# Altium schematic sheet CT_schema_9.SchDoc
size 147 x 119 mm
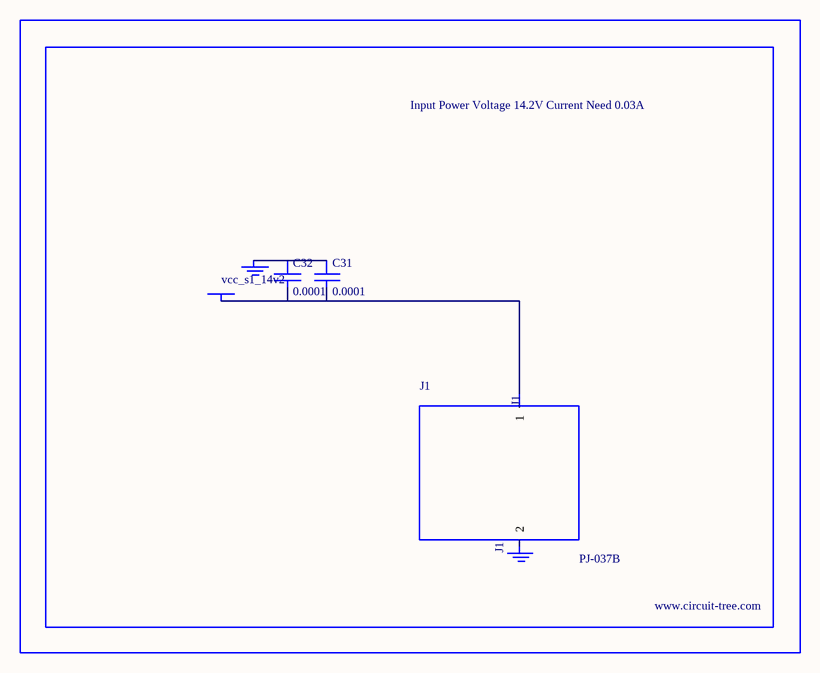
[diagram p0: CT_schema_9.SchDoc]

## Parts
BORDER8  (no value)
C31  0.0001  [EXV-9H]
C32  0.0001  [EXV-9H]
GND_INSTANCE_8_0  (no value)
GND_INSTANCE_8_1  (no value)
J1  PJ-037B  [PJ-037B_PACKAGE]
POWER_INSTANCE_8_0  vcc_s1_14v2

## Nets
NetC31_1: C31.1 C32.1 GND_INSTANCE_8_0.0(GND)
NetC31_2: C31.2 C32.2 J1.1 POWER_INSTANCE_8_0.0(PWR)

Not connected (* = marked no-connect by the designer): GND_INSTANCE_8_1 0(GND); J1 2

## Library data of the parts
BORDER8 = BORDER_PAGE8
C31 C32 = EDK107M035A9HAA
GND_INSTANCE_8_0 GND_INSTANCE_8_1 = GND
POWER_INSTANCE_8_0 = PWR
